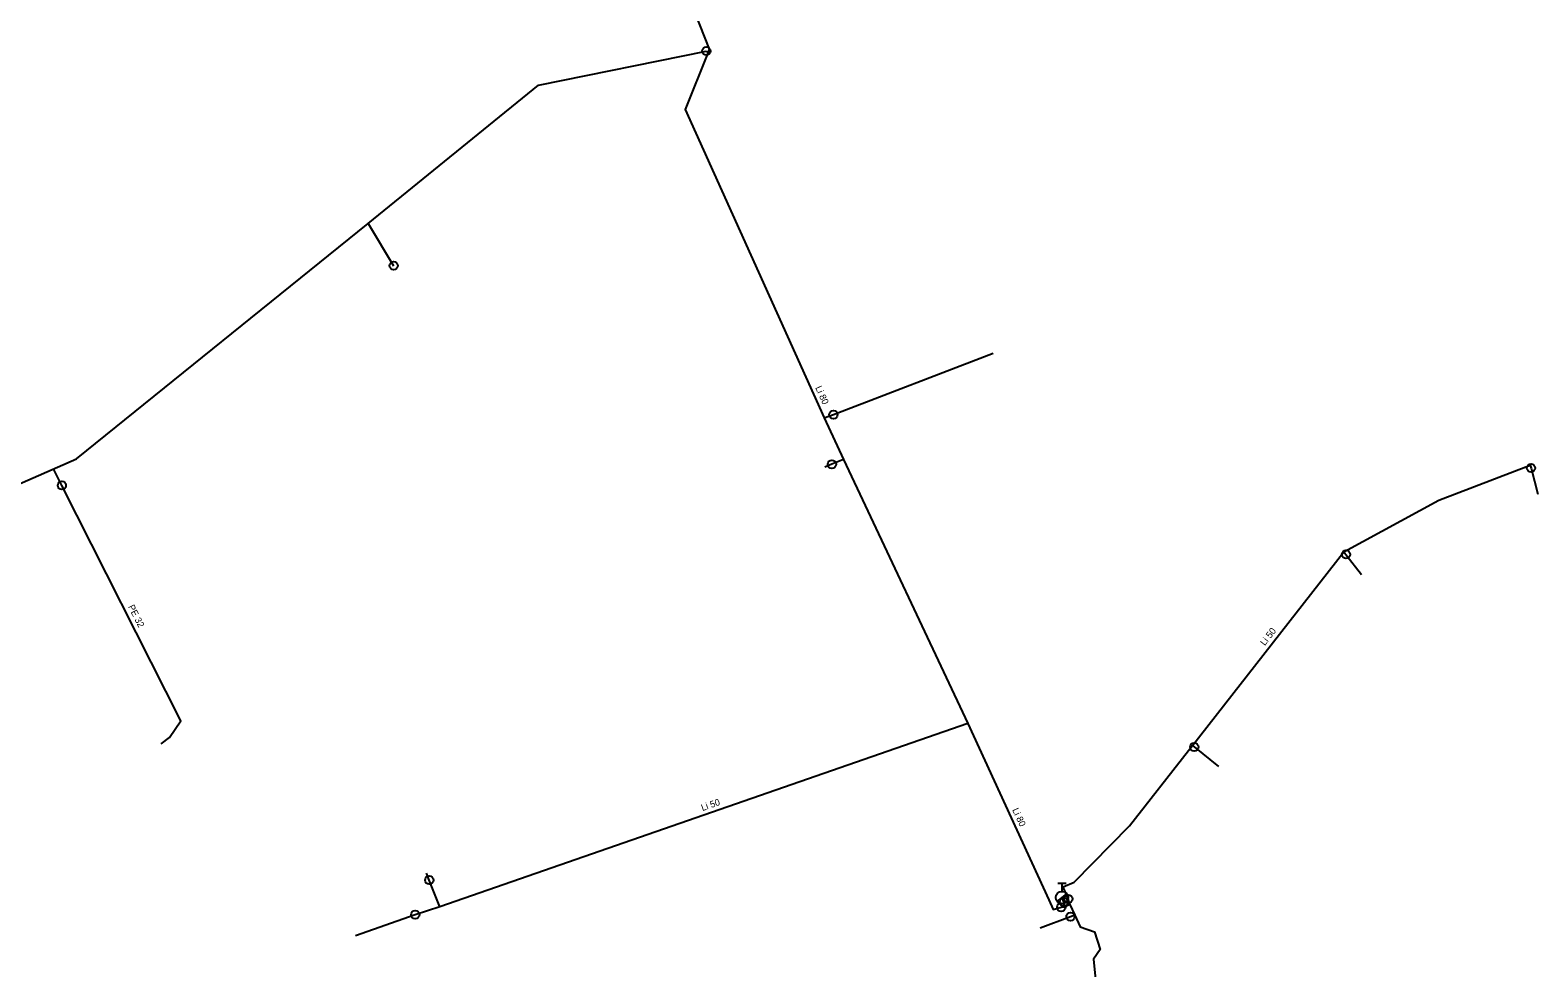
# Model space of a CAD drawing. Extents: x -783658 to -783200, y -1065250 to -1064865.
# Drawn here: x -783531.5 to -783440.8, y -1065158.1 to -1065101.7 of the extents above; entities that cross this region are included whole.
import ezdxf

# ---------------------------------------------------------------- set-up
doc = ezdxf.new("R2010")
doc.units = 0
for name, color, linetype in [('Hydranty', 7, 'Continuous'), ('Popis vodovodních řadů', 7, 'Continuous'), ('Vod přípojky-voda pitná', 7, 'Continuous'), ('Vodovodní řad', 7, 'Continuous'), ('Vodovodní šoupata', 7, 'Continuous')]:
    doc.layers.add(name, color=color, linetype=linetype)

msp = doc.modelspace()

# ---------------------------------------------------------------- linework, layer by layer
at = {"layer": 'Hydranty'}
for p, q in [((-783469.64, -1065152.985), (-783469.14, -1065152.985)), ((-783469.39, -1065153.485), (-783469.39, -1065152.985)), ((-783469.684, -1065154.091), (-783469.094, -1065153.628))]:
    msp.add_line(p, q, dxfattribs=at)
msp.add_circle((-783469.39, -1065153.86), 0.375, dxfattribs=at)
at = {"layer": 'Vod přípojky-voda pitná'}
for points in [[(-783511.16, -1065113.31), (-783509.62, -1065115.85)], [(-783483.71, -1065125), (-783483.15, -1065124.81), (-783473.54, -1065121.11)], [(-783482.54, -1065127.5), (-783483.24, -1065127.79), (-783483.67, -1065127.97)], [(-783523.62, -1065144.61), (-783523.12, -1065144.24), (-783522.42, -1065143.22), (-783529.59, -1065129.07), (-783530.09, -1065128.07)], [(-783441.22, -1065127.85), (-783441.16, -1065128.02), (-783440.75, -1065129.6)], [(-783452.43, -1065133.06), (-783452.3, -1065133.22), (-783451.36, -1065134.42)], [(-783461.54, -1065144.71), (-783461.43, -1065144.8), (-783459.98, -1065145.97)], [(-783506.84, -1065154.41), (-783507.48, -1065152.81), (-783507.65, -1065152.4)], [(-783506.84, -1065154.41), (-783508.32, -1065154.89), (-783511.92, -1065156.16)], [(-783468.62, -1065154.92), (-783468.88, -1065155.01), (-783470.71, -1065155.71)]]:
    msp.add_lwpolyline(points, dxfattribs=at)
at = {"layer": 'Vodovodní řad'}
for points in [[(-783491.15, -1065093.26), (-783492.05, -1065099.19), (-783490.62, -1065102.82), (-783490.69, -1065103)], [(-783584.44, -1065152.88), (-783566.77, -1065145.37), (-783545.99, -1065135.02), (-783528.71, -1065127.46), (-783511.16, -1065113.31), (-783500.9, -1065104.99), (-783490.8, -1065102.94)], [(-783490.69, -1065103), (-783492.07, -1065106.45), (-783483.71, -1065125), (-783482.54, -1065127.5), (-783475.06, -1065143.38)], [(-783490.8, -1065102.94), (-783490.69, -1065103)], [(-783469.01, -1065153.94), (-783469.33, -1065153.22), (-783468.66, -1065152.93), (-783465.33, -1065149.54), (-783461.78, -1065145.01), (-783461.54, -1065144.71), (-783452.43, -1065133.06), (-783446.71, -1065129.96), (-783441.22, -1065127.85)], [(-783475.06, -1065143.38), (-783506.84, -1065154.41)], [(-783475.06, -1065143.38), (-783470.19, -1065153.99)], [(-783469.28, -1065154.13), (-783469.39, -1065153.86)], [(-783468.91, -1065154.27), (-783469.01, -1065153.94)], [(-783470.19, -1065153.99), (-783469.92, -1065154.58), (-783469.44, -1065154.44)], [(-783469.44, -1065154.44), (-783469.21, -1065154.41)], [(-783469.21, -1065154.41), (-783469.28, -1065154.13)], [(-783468.91, -1065154.27), (-783469.21, -1065154.41)], [(-783468.91, -1065154.27), (-783468.62, -1065154.92), (-783468.29, -1065155.62), (-783467.44, -1065155.92), (-783467.1, -1065156.98), (-783467.5, -1065157.57), (-783467.01, -1065162.46)]]:
    msp.add_lwpolyline(points, dxfattribs=at)
at = {"layer": 'Vodovodní šoupata'}
for centre in [(-783490.8, -1065102.94), (-783509.62, -1065115.85), (-783483.15, -1065124.81), (-783483.24, -1065127.79), (-783441.16, -1065128.02), (-783529.59, -1065129.07), (-783452.3, -1065133.22), (-783461.43, -1065144.8), (-783507.48, -1065152.81), (-783469.28, -1065154.13), (-783469.01, -1065153.94), (-783508.32, -1065154.89), (-783469.44, -1065154.44), (-783468.88, -1065155.01)]:
    msp.add_circle(centre, 0.25, dxfattribs=at)

# ---------------------------------------------------------------- texts
at = {"layer": 'Popis vodovodních řadů'}
for s, rotation, p in [('Li 80', 294.25984, (-783484.252, -1065123.188)), ('PE 32', 296.87196, (-783525.615, -1065136.363)), ('Li 50', 51.97551, (-783457.189, -1065138.74)), ('Li 50', 19.14054, (-783491.032, -1065148.659)), ('Li 80', 294.65517, (-783472.398, -1065148.581))]:
    msp.add_text(s, height=0.4, rotation=rotation, dxfattribs=at).set_placement(p)

doc.saveas('drawing.dxf')
